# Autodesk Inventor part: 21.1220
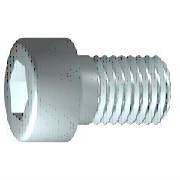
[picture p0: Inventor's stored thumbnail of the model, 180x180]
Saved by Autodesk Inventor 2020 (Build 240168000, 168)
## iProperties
Created: 2006-02
Part Number: 21.1220
Material: Steel, Mild
Description: M5 X 12 SHCS
Document SubType Name: Modeling
Standard: DIN 7984
Designer: Andy Moles
Standards Organization: DIN
Language: en-US
Size Designation: M5 x 12
Categories: <MemberInstance><Categories><Category DisplayName="Fasteners" InternalName="e4da775c-781d-43d5-af7c-5136215cf5a6" Mnemonic="FSTN"><Category DisplayName="Bolts"
Density: 7.85 g/cm^3
Mass: 3.19467 g
Surface Area: 4.14957 cm^2
Volume: 0.406964 cm^3
Appearance: Zinc
Author: Andy Moles
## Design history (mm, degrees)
sketch "Sketch1"
  geometry: L1 (0.2, 0)-(12, 0); L2 (12, 0)-(12, 2.5); L3 (12, 2.5)-(2.4, 2.5); L4 (2.4, 2.5)-(1.909, 2.5); L5 (1.909, 2.5)-(0, 2.5); L6 (0, 2.5)-(0, 4.25); L7 (0, 4.25)-(-3.5, 4.25); L8 (-3.5, 4.25)-(-3.5, 1.732); L9 (-3.5, 1.732)-(-0.8, 1.732); L10 (-0.8, 1.732)-(0.2, 0); L11 (-5.05, 0)-(16.65, 0) reference; L12 (0, -0.425)-(0, 5.525) reference; L13 (2.4, 2.5)-(0, 2.5)
  constraints: 22 end point, 6 parallel, 2 collinear, 2 perpendicular, 1 horizontal, 1 point on line
  dimensions: "d1" = 9.6 distance from line of L3.end L2 (= GEL); "d2" = 0.49086 distance of L4.end L3.end (computed from GAL); "d3" = 3.5 distance between parallel lines of L8 L6 (= KOH); "d4" = 2.7 distance of L8.end L9.end (= INTI); "d5" = 60 deg angle of L10 L1; "d6" = 5 diameter of L3 L1 (= GD); "d7" = 5 diameter of L5 L1 (= BDM); "d8" = 3.4641 diameter of L9 L1 (= 1.1547 x SW); "d9" = 8.5 diameter of L7 L1 (= KOD); "d26" = 12 distance between parallel lines of L12 L2 (= NLG)
revolve "Body" sketch "Sketch1" stored, may be unused: angle "d10" = 90 deg
sketch "Sketch2"
  geometry: L1 (0, -5.1)-(0, 6.8) reference; L2 (-5.1, 0)-(6.8, 0) reference; L3 (1.732, 0)-(0.866, -1.5); L4 (0.866, -1.5)-(-0.866, -1.5); L5 (-0.866, -1.5)-(-1.732, 0); L6 (-1.732, 0)-(-0.866, 1.5); L7 (-0.866, 1.5)-(0.866, 1.5); L8 (0.866, 1.5)-(1.732, 0); 2 further points
  constraints: 12 end point, 1 coincident, 1 horizontal alignment, 1 point on line, 12 other
extrude "Slot" join sketch "Sketch2" stored distance "d11" = 10; taper "d12" = 0 deg
workplane "Work Plane1"
body "Solid1"
fillet "Fillet1" dims "d17" = 0.5 (= RR)
feature "Thread" dims "d13" = 16, "d14" = 0
chamfer "Chamfer1" distance "d15" = 0.49076 (= -0.5 x SPD + 0.5 x GD); stored, may be unused: second distance "d16" = 0.49076 (= GUL), angle "d27" = 45 deg
other parameters: "GD" = 5 (= NND) [user parameter; used in 2 equation terms], "NLG" = 12 [user parameter; used in 1 equation term], "GEL" = 9.6 [user parameter; used in 1 equation term], "KOD" = 8.5 [user parameter; used in 1 equation term], "KOH" = 3.5 [user parameter; used in 1 equation term], "INTI" = 2.7 [user parameter; used in 1 equation term], "GAL" = 0.49076 (= 0.61345 x PTC) [user parameter; used in 1 equation term], "GUL" = 0.49076 (= 0.61345 x PTC) [user parameter; used in 1 equation term], "BDM" = 5 (= NND) [user parameter; used in 1 equation term], "SW" = 3 [user parameter; used in 2 equation terms], "RR" = 0.5 [user parameter; used in 1 equation term], "SPD" = 4.01848 (= NND - 1.2269 x PTC) [user parameter; used in 1 equation term], "d19" = 0, "d28" = 0, "d29" = 0, "TOA" = 30 deg [user parameter], "GD1" = 4.01848 (= THREADDIA - 1.2269 x PTC) [user parameter], "THREADDIA" = 5 [user parameter; used in 1 equation term], "FAWI" = 45 deg [user parameter], "ANG" = 120 deg [user parameter], "TPU" = 12.5 (computed from PTC) [user parameter], "PTC" = 0.8 [user parameter; used in 5 equation terms], "NND" = 5 [user parameter; used in 3 equation terms], "E0" = 3.465 (= 1.155 x SW) [user parameter]
